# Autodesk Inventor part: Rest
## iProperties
Created: 2008-12
Part Number: Rest
Document SubType Name: Modeling
Designer: Ed O'Halloran
Density: 1 g/cm^3
Author: Ed O'Halloran
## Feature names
1. Extrusion1
2. Revolution1
3. Fillet1
4. Shell1
5. Fillet2
